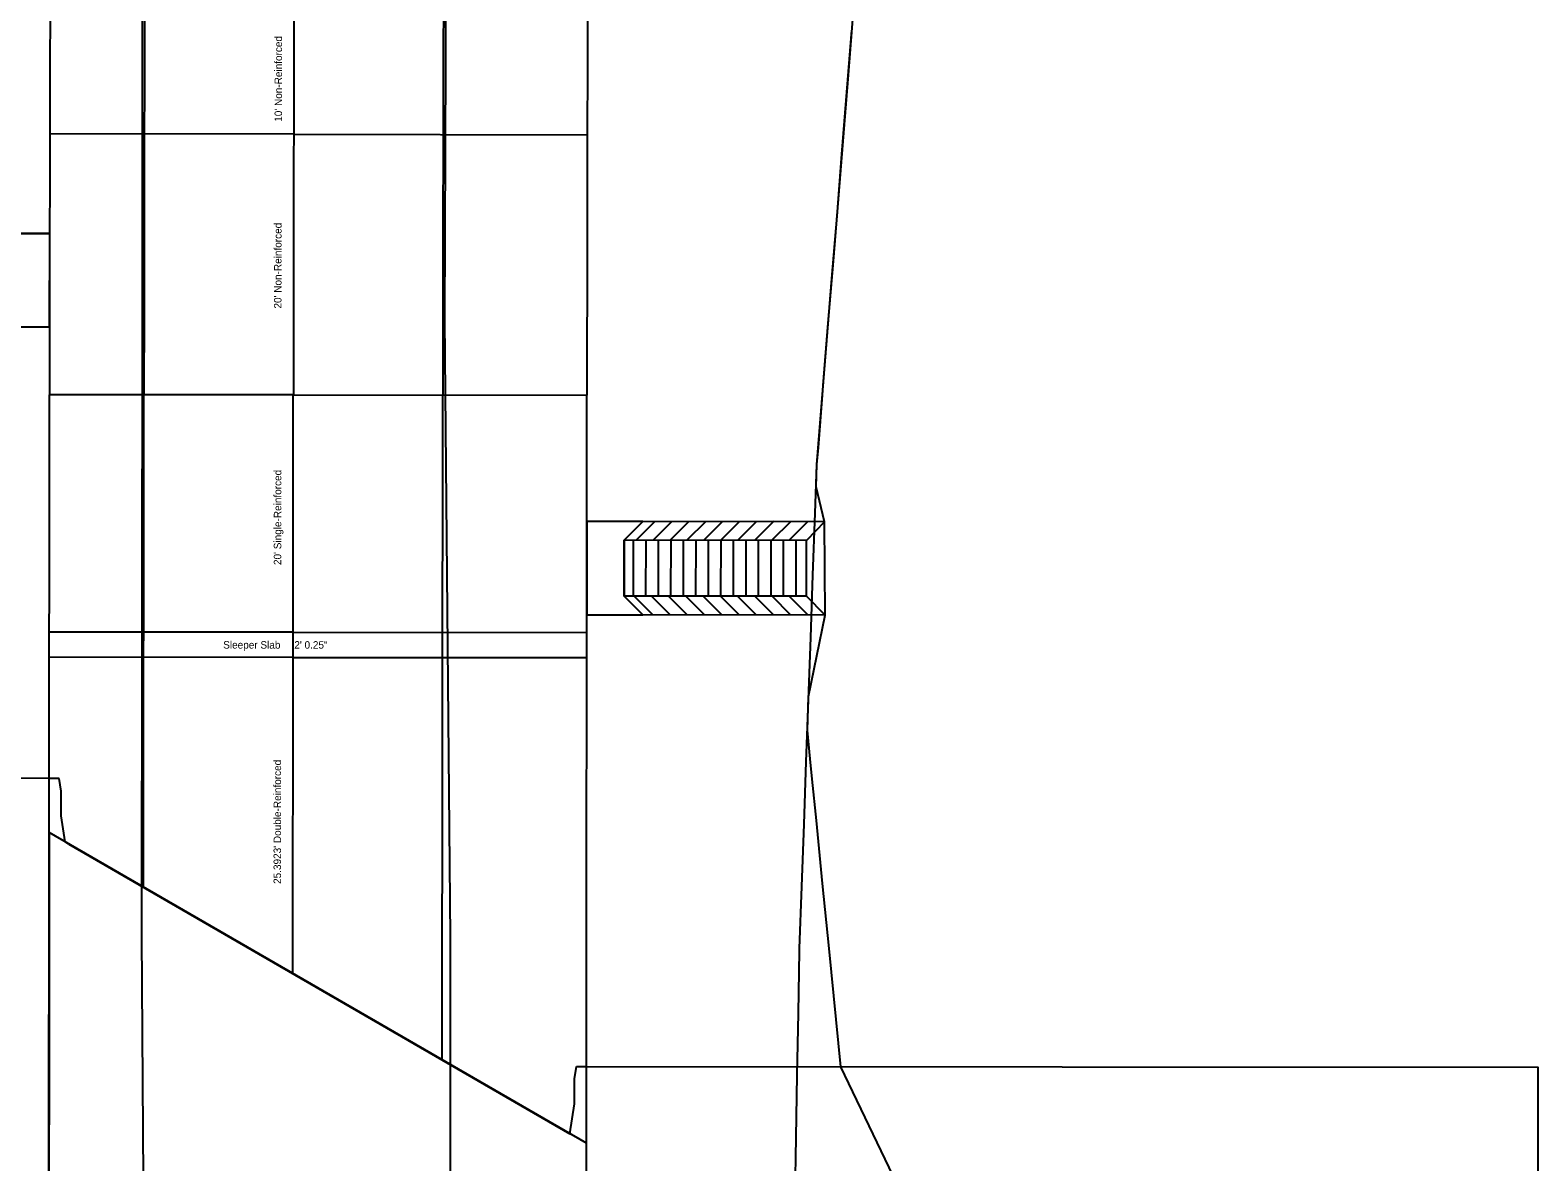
# Model space of a CAD drawing. Extents: x 18543285 to 18543485, y 7434209 to 7435438.
# Drawn here: x 18543363.7 to 18543484.8, y 7434880 to 7434970.9 of the extents above; entities that cross this region are included whole.
import ezdxf

# ---------------------------------------------------------------- set-up
doc = ezdxf.new("R2010")
doc.units = 0
for name, color, linetype in [('Contours Major', 7, 'Continuous'), ('Dimensions', 7, 'Continuous'), ('Draft_1', 7, 'Continuous'), ('Terrain', 7, 'Continuous'), ('TL_DitchFront', 7, 'Continuous'), ('TL_ForeSlope', 7, 'Continuous'), ('TL_Grading', 7, 'Continuous'), ('TL_GroundIntercept', 7, 'Continuous')]:
    doc.layers.add(name, color=color, linetype=linetype)

msp = doc.modelspace()

# ---------------------------------------------------------------- linework, layer by layer
at = {"layer": 'Contours Major'}
for p, q in [((18543365.23, 7434906.43), (18543365.25, 7434941.59)), ((18543408.38, 7434881.48), (18543408.42, 7434941.56))]:
    msp.add_line(p, q, dxfattribs=at)
for radius in [17247.01, 17203.84]:
    msp.add_arc((18560612.26, 7434930.39), radius, 179.859872, 179.962789, dxfattribs=at)
at = {"layer": 'Dimensions'}
for p, q in [((18543429.31, 7434965.89), (18543429.71, 7434970.88)), ((18543428.91, 7434960.91), (18543429.31, 7434965.89)), ((18543428.51, 7434955.93), (18543428.91, 7434960.91)), ((18543428.1, 7434950.94), (18543428.51, 7434955.93)), ((18543427.7, 7434945.96), (18543428.1, 7434950.94)), ((18543427.3, 7434940.98), (18543427.7, 7434945.96)), ((18543426.9, 7434935.99), (18543427.3, 7434940.98)), ((18543426.76, 7434932.09), (18543426.9, 7434935.99)), ((18543426.58, 7434927.1), (18543426.76, 7434932.09)), ((18543426.4, 7434922.1), (18543426.58, 7434927.1)), ((18543426.22, 7434917.1), (18543426.4, 7434922.1)), ((18543426.04, 7434912.11), (18543426.22, 7434917.1)), ((18543425.86, 7434907.11), (18543426.04, 7434912.11)), ((18543425.68, 7434902.11), (18543425.86, 7434907.11)), ((18543425.5, 7434897.12), (18543425.68, 7434902.11)), ((18543425.41, 7434891.94), (18543425.5, 7434896.94)), ((18543425.5, 7434896.94), (18543425.5, 7434897.12)), ((18543425.32, 7434886.94), (18543425.41, 7434891.94)), ((18543425.23, 7434881.94), (18543425.32, 7434886.94)), ((18543425.14, 7434876.94), (18543425.23, 7434881.94))]:
    msp.add_line(p, q, dxfattribs=at)
at = {"layer": 'Draft_1'}
for points in [[(18543371.92, 7435437.85), (18543375.17, 7435388.86), (18543377.54, 7435354.86), (18543376.4, 7435304.32), (18543375.52, 7435249.83), (18543374.8, 7435202.03), (18543374, 7435154.29), (18543373.47, 7435100.8), (18543373.17, 7435054.8), (18543372.87, 7435002.38), (18543372.67, 7434996.87), (18543372.7, 7434948.18), (18543372.65, 7434898.09), (18543372.81, 7434874.76), (18543384.75, 7434868.26)], [(18543404.08, 7435437.2), (18543402.71, 7435386.63), (18543401.61, 7435352.24), (18543400.62, 7435302.3), (18543399.36, 7435249.31), (18543398.8, 7435202.17), (18543398.16, 7435153.5), (18543397.61, 7435102.6), (18543397.31, 7435054.09), (18543397.17, 7435001.8), (18543397.18, 7434996), (18543396.99, 7434947.58), (18543397.43, 7434898.03), (18543397.44, 7434860.72), (18543384.75, 7434868.26)]]:
    msp.add_lwpolyline(points, dxfattribs=at)
at = {"layer": 'TL_DitchFront'}
msp.add_line((18543408.38, 7434881.48), (18543365.23, 7434906.43), dxfattribs=at)
for points in [[(18543284.72, 7434759.35), (18543365.13, 7434759.3), (18543365.13, 7434759.3), (18543365.13, 7434759.3), (18543365.23, 7434910.77), (18543284.82, 7434910.82)], [(18543365.14, 7434765.47), (18543408.29, 7434740.52), (18543408.38, 7434881.48), (18543365.23, 7434906.43)], [(18543484.7, 7434736.13), (18543408.29, 7434736.18), (18543408.29, 7434736.18), (18543408.29, 7434736.18), (18543408.38, 7434887.64), (18543484.8, 7434887.6)]]:
    msp.add_lwpolyline(points, close=True, dxfattribs=at)
at = {"layer": 'TL_ForeSlope'}
for p, q in [((18543384.86, 7434962.52), (18543365.28, 7434962.56)), ((18543384.86, 7434962.52), (18543408.45, 7434962.48)), ((18543384.84, 7434941.58), (18543365.25, 7434941.59)), ((18543372.81, 7434902.05), (18543372.84, 7434941.59)), ((18543384.82, 7434922.52), (18543384.84, 7434941.58)), ((18543384.84, 7434941.58), (18543408.42, 7434941.56)), ((18543396.8, 7434888.17), (18543396.84, 7434941.57)), ((18543384.82, 7434922.52), (18543365.24, 7434922.54)), ((18543384.82, 7434920.5), (18543384.82, 7434922.52)), ((18543384.82, 7434922.52), (18543408.41, 7434922.51)), ((18543384.82, 7434920.5), (18543365.24, 7434920.52)), ((18543384.81, 7434895.11), (18543384.82, 7434920.5)), ((18543384.82, 7434920.5), (18543408.41, 7434920.49)), ((18543366.02, 7434910.77), (18543365.23, 7434910.77)), ((18543366.19, 7434909.77), (18543366.02, 7434910.77)), ((18543366.19, 7434907.77), (18543366.19, 7434909.77)), ((18543366.51, 7434905.69), (18543366.19, 7434907.77)), ((18543366.81, 7434905.51), (18543366.51, 7434905.69)), ((18543366.81, 7434905.51), (18543407.05, 7434882.25)), ((18543407.43, 7434886.65), (18543407.59, 7434887.65)), ((18543407.59, 7434887.65), (18543408.38, 7434887.64)), ((18543407.42, 7434884.65), (18543407.43, 7434886.65)), ((18543407.05, 7434882.25), (18543407.42, 7434884.65))]:
    msp.add_line(p, q, dxfattribs=at)
for radius, start, end in [(17239.42, 179.859872, 179.962789), (17227.42, 179.859872, 179.893131), (17215.42, 179.859872, 179.962789), (17227.42, 179.893131, 179.959648), (17227.42, 179.959648, 179.962789)]:
    msp.add_arc((18560612.26, 7434930.39), radius, start, end, dxfattribs=at)
at = {"layer": 'TL_Grading'}
for p, q in [((18543350.91, 7434954.56), (18543365.27, 7434954.54)), ((18543365.25, 7434947.04), (18543365.27, 7434954.54)), ((18543350.85, 7434947.06), (18543365.25, 7434947.04)), ((18543427.5, 7434931.4), (18543408.41, 7434931.42)), ((18543408.41, 7434931.42), (18543408.41, 7434923.92)), ((18543412.91, 7434931.41), (18543411.41, 7434929.91)), ((18543413.87, 7434931.41), (18543412.37, 7434929.91)), ((18543415.23, 7434931.41), (18543413.73, 7434929.91)), ((18543416.6, 7434931.41), (18543415.1, 7434929.91)), ((18543417.96, 7434931.41), (18543416.46, 7434929.91)), ((18543419.32, 7434931.41), (18543417.82, 7434929.91)), ((18543420.69, 7434931.41), (18543419.19, 7434929.91)), ((18543422.05, 7434931.41), (18543420.55, 7434929.91)), ((18543421.91, 7434929.91), (18543423.41, 7434931.41)), ((18543424.78, 7434931.4), (18543423.28, 7434929.91)), ((18543427.5, 7434931.4), (18543423.41, 7434931.41)), ((18543426.14, 7434931.4), (18543424.64, 7434929.9)), ((18543427.5, 7434931.4), (18543426.07, 7434929.9)), ((18543426.07, 7434929.9), (18543411.41, 7434929.91)), ((18543411.41, 7434929.91), (18543411.41, 7434925.41)), ((18543412.16, 7434925.41), (18543412.16, 7434929.91)), ((18543413.16, 7434925.41), (18543413.17, 7434929.91)), ((18543414.17, 7434925.41), (18543414.17, 7434929.91)), ((18543415.17, 7434925.41), (18543415.18, 7434929.91)), ((18543416.18, 7434925.41), (18543416.18, 7434929.91)), ((18543417.18, 7434925.41), (18543417.19, 7434929.91)), ((18543418.19, 7434925.41), (18543418.19, 7434929.91)), ((18543419.19, 7434925.41), (18543419.2, 7434929.91)), ((18543420.2, 7434925.41), (18543420.2, 7434929.91)), ((18543421.2, 7434925.41), (18543421.21, 7434929.91)), ((18543426.07, 7434929.9), (18543421.91, 7434929.91)), ((18543422.21, 7434925.41), (18543422.21, 7434929.91)), ((18543423.21, 7434925.41), (18543423.22, 7434929.91)), ((18543424.22, 7434925.41), (18543424.22, 7434929.91)), ((18543425.22, 7434925.4), (18543425.23, 7434929.9)), ((18543426.06, 7434925.41), (18543426.07, 7434929.91)), ((18543412.91, 7434923.91), (18543411.41, 7434925.42)), ((18543426.06, 7434925.41), (18543411.41, 7434925.41)), ((18543413.71, 7434923.91), (18543412.21, 7434925.41)), ((18543415.1, 7434923.91), (18543413.6, 7434925.41)), ((18543416.48, 7434923.91), (18543414.98, 7434925.41)), ((18543417.87, 7434923.91), (18543416.37, 7434925.41)), ((18543419.25, 7434923.91), (18543417.75, 7434925.41)), ((18543420.64, 7434923.91), (18543419.14, 7434925.41)), ((18543422.02, 7434923.91), (18543420.52, 7434925.41)), ((18543423.41, 7434923.91), (18543421.91, 7434925.41)), ((18543423.41, 7434923.91), (18543421.91, 7434925.41)), ((18543426.06, 7434925.41), (18543421.91, 7434925.41)), ((18543424.79, 7434923.9), (18543423.29, 7434925.41)), ((18543426.18, 7434923.9), (18543424.68, 7434925.41)), ((18543427.56, 7434923.9), (18543426.06, 7434925.41)), ((18543427.56, 7434923.9), (18543408.41, 7434923.92)), ((18543427.56, 7434923.9), (18543423.41, 7434923.91))]:
    msp.add_line(p, q, dxfattribs=at)
for points in [[(18543362.26, 7434953.04), (18543362.26, 7434948.54), (18543360.75, 7434947.05), (18543365.25, 7434947.04), (18543365.27, 7434954.54), (18543360.77, 7434954.55), (18543362.26, 7434953.04)], [(18543411.41, 7434925.41), (18543411.41, 7434929.91), (18543412.91, 7434931.41), (18543408.41, 7434931.42), (18543408.41, 7434923.92), (18543412.91, 7434923.91), (18543411.41, 7434925.41)]]:
    msp.add_lwpolyline(points, dxfattribs=at)
at = {"layer": 'TL_GroundIntercept'}
for points in [[(18543428.81, 7434887.63), (18543427.87, 7434897.12), (18543427.35, 7434902.35), (18543426.85, 7434907.39), (18543426.52, 7434910.71), (18543426.36, 7434912.35), (18543426.13, 7434914.63), (18543426.23, 7434917.35), (18543427.56, 7434923.9), (18543427.56, 7434923.9), (18543427.5, 7434931.4), (18543426.84, 7434934.2), (18543426.84, 7434934.2), (18543426.9, 7434935.99), (18543427.01, 7434937.35), (18543427.35, 7434941.55), (18543427.41, 7434942.35), (18543427.81, 7434947.34), (18543428.22, 7434952.32), (18543428.62, 7434957.31), (18543429.42, 7434967.28), (18543430.14, 7434976.23)], [(18543426.37, 7434736.17), (18543438.19, 7434761.05), (18543441.09, 7434774.96), (18543443.08, 7434857.91), (18543428.81, 7434887.63)]]:
    msp.add_lwpolyline(points, dxfattribs=at)

# ---------------------------------------------------------------- texts
at = {"layer": 'Terrain'}
for s, rotation, p in [("10' Non-Reinforced", 89.9628, (18543383.93, 7434963.52)), ("20' Non-Reinforced", 89.9628, (18543383.89, 7434948.52)), ("20' Single-Reinforced", 89.9628, (18543383.87, 7434927.92)), ('Sleeper Slab     2\' 0.25"', 359.9628, (18543379.21, 7434921.21)), ("25.3923' Double-Reinforced", 89.9628, (18543383.85, 7434902.31))]:
    msp.add_text(s, height=0.6, rotation=rotation, dxfattribs=at).set_placement(p)

doc.saveas('drawing.dxf')
